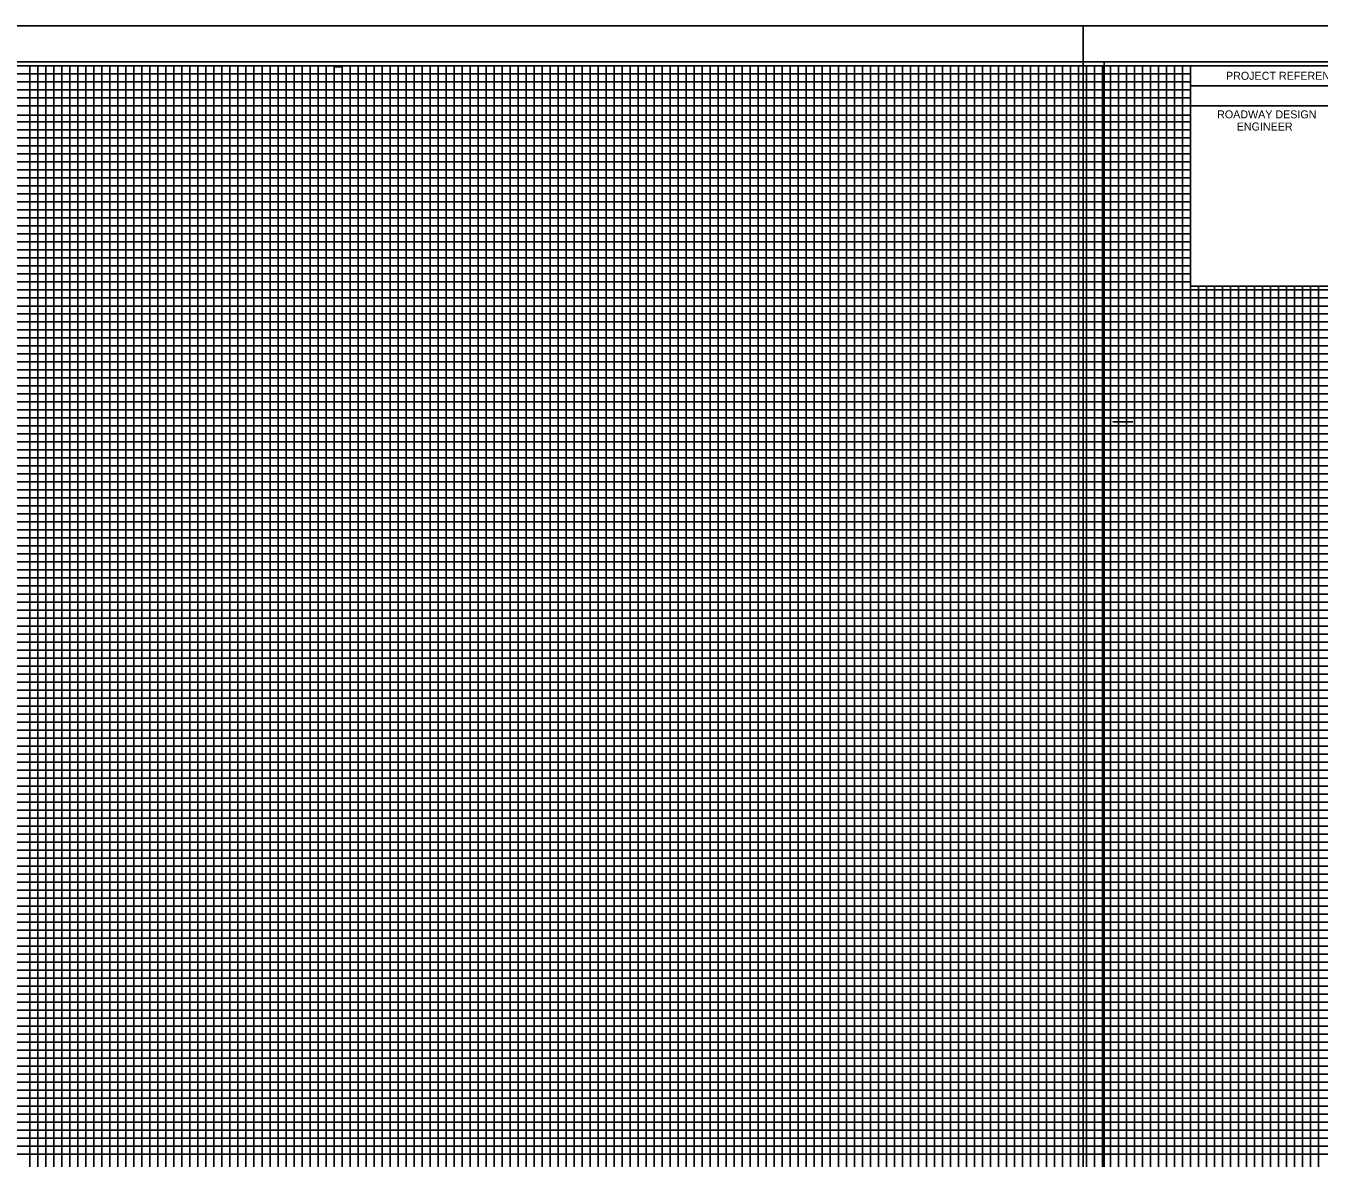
# Model space of a CAD drawing. Extents: x 2345490 to 2436403, y 465165 to 573888.
# Drawn here: x 2382289 to 2383097, y 510797 to 511504 of the extents above; entities that cross this region are included whole.
import ezdxf

# ---------------------------------------------------------------- set-up
doc = ezdxf.new("R2010")
doc.units = 0
for name, color, linetype in [('Old_Level_18', 7, 'Continuous'), ('Old_Level_40', 7, 'Continuous'), ('Old_Level_41', 7, 'Continuous'), ('Old_Level_42', 7, 'Continuous'), ('Old_Level_43', 7, 'Continuous'), ('Old_Level_44', 7, 'Continuous'), ('Old_Level_50', 7, 'Continuous'), ('Old_Level_51', 7, 'Continuous')]:
    doc.layers.add(name, color=color, linetype=linetype)

msp = doc.modelspace()

# ---------------------------------------------------------------- linework, layer by layer
at = {"layer": 'Old_Level_18'}
msp.add_lwpolyline([(2383216.79875, 511479.3835), (2381716.79875, 511479.3835), (2381716.79875, 510429.3835), (2383216.79875, 510429.3835)], close=True, dxfattribs=at)
at = {"layer": 'Old_Level_40'}
msp.add_line((2383016.74875, 511466.8335), (2383216.79875, 511466.8335), dxfattribs=at)
for points in [[(2383016.74875, 511479.3835), (2383216.79875, 511479.3835), (2383216.79875, 511454.3335), (2383016.74875, 511454.3335)], [(2383016.74875, 511454.3335), (2383116.79875, 511454.3335), (2383116.79875, 511341.8335), (2383016.74875, 511341.8335)]]:
    msp.add_lwpolyline(points, close=True, dxfattribs=at)
at = {"layer": 'Old_Level_41'}
msp.add_line((2382968.29875, 511256.8835), (2382980.79875, 511256.8835), dxfattribs=at)
for points in [[(2382291.79875, 510454.3835), (2382291.79875, 511479.3835), (2382341.79875, 511479.3835), (2382341.79875, 510454.3835)], [(2382316.79875, 510454.3835), (2382316.79875, 511479.3835), (2382366.79875, 511479.3835), (2382366.79875, 510454.3835)], [(2382391.79875, 510454.3835), (2382391.79875, 511479.3835), (2382441.79875, 511479.3835), (2382441.79875, 510454.3835)], [(2382416.79875, 510454.3835), (2382416.79875, 511479.3835), (2382466.79875, 511479.3835), (2382466.79875, 510454.3835)], [(2382491.79875, 510454.3835), (2382491.79875, 511479.3835), (2382541.79875, 511479.3835), (2382541.79875, 510454.3835)], [(2382516.79875, 510454.3835), (2382516.79875, 511479.3835), (2382566.79875, 511479.3835), (2382566.79875, 510454.3835)], [(2382591.79875, 510454.3835), (2382591.79875, 511479.3835), (2382641.79875, 511479.3835), (2382641.79875, 510454.3835)], [(2382616.79875, 510454.3835), (2382616.79875, 511479.3835), (2382666.79875, 511479.3835), (2382666.79875, 510454.3835)], [(2382691.79875, 510454.3835), (2382691.79875, 511479.3835), (2382741.79875, 511479.3835), (2382741.79875, 510454.3835)], [(2382716.79875, 510454.3835), (2382716.79875, 511479.3835), (2382766.79875, 511479.3835), (2382766.79875, 510454.3835)], [(2382791.79875, 510454.3835), (2382791.79875, 511479.3835), (2382841.79875, 511479.3835), (2382841.79875, 510454.3835)], [(2382816.79875, 510454.3835), (2382816.79875, 511479.3835), (2382866.79875, 511479.3835), (2382866.79875, 510454.3835)], [(2382891.79875, 510454.3835), (2382891.79875, 511479.3835), (2382941.79875, 511479.3835), (2382941.79875, 510454.3835)], [(2382916.79875, 510454.3835), (2382916.79875, 511479.3835), (2382966.79875, 511479.3835), (2382966.79875, 510454.3835)], [(2382991.79875, 510454.3835), (2382991.79875, 511479.3835)], [(2383016.79875, 510454.3835), (2383016.79875, 511479.3835), (2383043.09875, 511479.3835)], [(2381716.79875, 511429.3835), (2383016.74875, 511429.3835)], [(2383016.74875, 511379.3835), (2381716.79875, 511379.3835), (2381716.79875, 511329.3335), (2383216.79875, 511329.3335)], [(2383216.79875, 511304.3835), (2381716.79875, 511304.3835), (2381716.79875, 511354.3835), (2383016.74875, 511354.3835)], [(2383041.79875, 511341.8335), (2383041.79875, 510454.3835), (2383091.79875, 510454.3835), (2383091.79875, 511341.8335)], [(2383216.79875, 511279.3835), (2381716.79875, 511279.3835), (2381716.79875, 511229.3835), (2383216.79875, 511229.3835)], [(2383216.79875, 511204.3835), (2381716.79875, 511204.3835), (2381716.79875, 511254.3835), (2383216.79875, 511254.3835)], [(2383216.79875, 511179.3835), (2381716.79875, 511179.3835), (2381716.79875, 511129.3835), (2383216.79875, 511129.3835)], [(2383216.79875, 511079.3835), (2381716.79875, 511079.3835), (2381716.79875, 511029.3835), (2383216.79875, 511029.3835)], [(2383216.79875, 510979.3835), (2381716.79875, 510979.3835), (2381716.79875, 510929.3835), (2383216.79875, 510929.3835)], [(2383216.79875, 510879.3835), (2381716.79875, 510879.3835), (2381716.79875, 510829.3835), (2383216.79875, 510829.3835)], [(2383216.79875, 510804.3835), (2381716.79875, 510804.3835), (2381716.79875, 510854.3835), (2383216.79875, 510854.3835)]]:
    msp.add_lwpolyline(points, dxfattribs=at)
at = {"layer": 'Old_Level_42'}
for points in [[(2383016.74875, 511404.3835), (2381716.89875, 511404.3835), (2381716.89875, 511454.3335), (2383016.74875, 511454.3335)], [(2383066.79875, 511341.8335), (2383066.79875, 510454.3835), (2383116.79875, 510454.3835), (2383116.79875, 511341.8335)], [(2383216.79875, 511104.3835), (2381716.79875, 511104.3835), (2381716.79875, 511154.3835), (2383216.79875, 511154.3835)], [(2383216.79875, 511004.3835), (2381716.79875, 511004.3835), (2381716.79875, 511054.3835), (2383216.79875, 511054.3835)], [(2383216.79875, 510904.3835), (2381716.79875, 510904.3835), (2381716.79875, 510954.3835), (2383216.79875, 510954.3835)]]:
    msp.add_lwpolyline(points, dxfattribs=at)
at = {"layer": 'Old_Level_43'}
for p, q in [((2383166.79875, 511299.3835), (2381766.79875, 511299.3835)), ((2381766.79875, 511294.3835), (2383166.79875, 511294.3835)), ((2383166.79875, 511274.3835), (2381766.79875, 511274.3835))]:
    msp.add_line(p, q, dxfattribs=at)
for points in [[(2382296.79875, 510454.3835), (2382296.79875, 511479.3835), (2382301.79875, 511479.3835), (2382301.79875, 510454.3835)], [(2382306.79875, 510454.3835), (2382306.79875, 511479.3835), (2382311.79875, 511479.3835), (2382311.79875, 510454.3835)], [(2382321.79875, 510454.3835), (2382321.79875, 511479.3835), (2382326.79875, 511479.3835), (2382326.79875, 510454.3835)], [(2382331.79875, 510454.3835), (2382331.79875, 511479.3835), (2382336.79875, 511479.3835), (2382336.79875, 510454.3835)], [(2382346.79875, 510454.3835), (2382346.79875, 511479.3835), (2382351.79875, 511479.3835), (2382351.79875, 510454.3835)], [(2382356.79875, 510454.3835), (2382356.79875, 511479.3835), (2382361.79875, 511479.3835), (2382361.79875, 510454.3835)], [(2382371.79875, 510454.3835), (2382371.79875, 511479.3835), (2382376.79875, 511479.3835), (2382376.79875, 510454.3835)], [(2382381.79875, 510454.3835), (2382381.79875, 511479.3835), (2382386.79875, 511479.3835), (2382386.79875, 510454.3835)], [(2382396.79875, 510454.3835), (2382396.79875, 511479.3835), (2382401.79875, 511479.3835), (2382401.79875, 510454.3835)], [(2382406.79875, 510454.3835), (2382406.79875, 511479.3835), (2382411.79875, 511479.3835), (2382411.79875, 510454.3835)], [(2382421.79875, 510454.3835), (2382421.79875, 511479.3835), (2382426.79875, 511479.3835), (2382426.79875, 510454.3835)], [(2382431.79875, 510454.3835), (2382431.79875, 511479.3835), (2382436.79875, 511479.3835), (2382436.79875, 510454.3835)], [(2382446.79875, 510454.3835), (2382446.79875, 511479.3835), (2382451.79875, 511479.3835), (2382451.79875, 510454.3835)], [(2382456.79875, 510454.3835), (2382456.79875, 511479.3835), (2382461.79875, 511479.3835), (2382461.79875, 510454.3835)], [(2382471.79875, 510454.3835), (2382471.79875, 511479.3835), (2382476.79875, 511479.3835), (2382476.79875, 510454.3835)], [(2382481.79875, 510454.3835), (2382481.79875, 511478.7835), (2382486.79875, 511478.7835), (2382486.79875, 510454.3835)], [(2382496.79875, 510454.3835), (2382496.79875, 511479.3835), (2382501.79875, 511479.3835), (2382501.79875, 510454.3835)], [(2382506.79875, 510454.3835), (2382506.79875, 511479.3835), (2382511.79875, 511479.3835), (2382511.79875, 510454.3835)], [(2382521.79875, 510454.3835), (2382521.79875, 511479.3835), (2382526.79875, 511479.3835), (2382526.79875, 510454.3835)], [(2382531.79875, 510454.3835), (2382531.79875, 511479.3835), (2382536.79875, 511479.3835), (2382536.79875, 510454.3835)], [(2382546.79875, 510454.3835), (2382546.79875, 511479.3835), (2382551.79875, 511479.3835), (2382551.79875, 510454.3835)], [(2382556.79875, 510454.3835), (2382556.79875, 511479.3835), (2382561.79875, 511479.3835), (2382561.79875, 510454.3835)], [(2382571.79875, 510454.3835), (2382571.79875, 511479.3835), (2382576.79875, 511479.3835), (2382576.79875, 510454.3835)], [(2382581.79875, 510454.3835), (2382581.79875, 511479.3835), (2382586.79875, 511479.3835), (2382586.79875, 510454.3835)], [(2382596.79875, 510454.3835), (2382596.79875, 511479.3835), (2382601.79875, 511479.3835), (2382601.79875, 510454.3835)], [(2382606.79875, 510454.3835), (2382606.79875, 511479.3835), (2382611.79875, 511479.3835), (2382611.79875, 510454.3835)], [(2382621.79875, 510454.3835), (2382621.79875, 511479.3835), (2382626.79875, 511479.3835), (2382626.79875, 510454.3835)], [(2382631.79875, 510454.3835), (2382631.79875, 511479.3835), (2382636.79875, 511479.3835), (2382636.79875, 510454.3835)], [(2382646.79875, 510454.3835), (2382646.79875, 511479.3835), (2382651.79875, 511479.3835), (2382651.79875, 510454.3835)], [(2382656.79875, 510454.3835), (2382656.79875, 511479.3835), (2382661.79875, 511479.3835), (2382661.79875, 510454.3835)], [(2382671.79875, 510454.3835), (2382671.79875, 511479.3835), (2382676.79875, 511479.3835), (2382676.79875, 510454.3835)], [(2382681.79875, 510454.3835), (2382681.79875, 511479.3835), (2382686.79875, 511479.3835), (2382686.79875, 510454.3835)], [(2382696.79875, 510454.3835), (2382696.79875, 511479.3835), (2382701.79875, 511479.3835), (2382701.79875, 510454.3835)], [(2382706.79875, 510454.3835), (2382706.79875, 511479.3835), (2382711.79875, 511479.3835), (2382711.79875, 510454.3835)], [(2382721.79875, 510454.3835), (2382721.79875, 511479.3835), (2382726.79875, 511479.3835), (2382726.79875, 510454.3835)], [(2382731.79875, 510454.3835), (2382731.79875, 511479.3835), (2382736.79875, 511479.3835), (2382736.79875, 510454.3835)], [(2382746.79875, 510454.3835), (2382746.79875, 511479.3835), (2382751.79875, 511479.3835), (2382751.79875, 510454.3835)], [(2382756.79875, 510454.3835), (2382756.79875, 511479.3835), (2382761.79875, 511479.3835), (2382761.79875, 510454.3835)], [(2382771.79875, 510454.3835), (2382771.79875, 511479.3835), (2382776.79875, 511479.3835), (2382776.79875, 510454.3835)], [(2382781.79875, 510454.3835), (2382781.79875, 511479.3835), (2382786.79875, 511479.3835), (2382786.79875, 510454.3835)], [(2382796.79875, 510454.3835), (2382796.79875, 511479.3835), (2382801.79875, 511479.3835), (2382801.79875, 510454.3835)], [(2382806.79875, 510454.3835), (2382806.79875, 511479.3835), (2382811.79875, 511479.3835), (2382811.79875, 510454.3835)], [(2382821.79875, 510454.3835), (2382821.79875, 511479.3835), (2382826.79875, 511479.3835), (2382826.79875, 510454.3835)], [(2382831.79875, 510454.3835), (2382831.79875, 511479.3835), (2382836.79875, 511479.3835), (2382836.79875, 510454.3835)], [(2382846.79875, 510454.3835), (2382846.79875, 511479.3835), (2382851.79875, 511479.3835), (2382851.79875, 510454.3835)], [(2382856.79875, 510454.3835), (2382856.79875, 511479.3835), (2382861.79875, 511479.3835), (2382861.79875, 510454.3835)], [(2382871.79875, 510454.3835), (2382871.79875, 511479.3835), (2382876.79875, 511479.3835), (2382876.79875, 510454.3835)], [(2382881.79875, 510454.3835), (2382881.79875, 511479.3835), (2382886.79875, 511479.3835), (2382886.79875, 510454.3835)], [(2382896.79875, 510454.3835), (2382896.79875, 511479.3835), (2382901.79875, 511479.3835), (2382901.79875, 510454.3835)], [(2382906.79875, 510454.3835), (2382906.79875, 511479.3835), (2382911.79875, 511479.3835), (2382911.79875, 510454.3835)], [(2382921.79875, 510454.3835), (2382921.79875, 511479.3835), (2382926.79875, 511479.3835), (2382926.79875, 510454.3835)], [(2382931.79875, 510454.3835), (2382931.79875, 511479.3835), (2382936.79875, 511479.3835), (2382936.79875, 510454.3835)], [(2382946.79875, 510454.3835), (2382946.79875, 511479.3835), (2382951.79875, 511479.3835), (2382951.79875, 510454.3835)], [(2382956.79875, 510454.3835), (2382956.79875, 511479.3835), (2382961.79875, 511479.3835), (2382961.79875, 510454.3835)], [(2382971.79875, 510454.3835), (2382971.79875, 511479.3835), (2382976.79875, 511479.3835), (2382976.79875, 510454.3835)], [(2382981.79875, 510454.3835), (2382981.79875, 511479.3835), (2382986.79875, 511479.3835), (2382986.79875, 510454.3835)], [(2382996.79875, 510454.3835), (2382996.79875, 511479.3835), (2383001.79875, 511479.3835), (2383001.79875, 510454.3835)], [(2383006.79875, 510454.3835), (2383006.79875, 511479.3835), (2383011.79875, 511479.3835), (2383011.79875, 510454.3835)], [(2383016.74875, 511474.3835), (2381766.79875, 511474.3835), (2381766.79875, 511469.3835), (2383016.74875, 511469.3835)], [(2383016.74875, 511464.3835), (2381766.79875, 511464.3835), (2381766.79875, 511459.3835), (2383016.74875, 511459.3835)], [(2383016.74875, 511448.6335), (2381767.79875, 511448.6335), (2381767.79875, 511444.3835), (2383016.74875, 511444.3835)], [(2383016.74875, 511439.3835), (2381766.79875, 511439.3835), (2381766.79875, 511434.3835), (2383016.74875, 511434.3835)], [(2383016.74875, 511424.3835), (2381766.79875, 511424.3835), (2381766.79875, 511419.3835), (2383016.74875, 511419.3835)], [(2383016.74875, 511414.3835), (2381766.79875, 511414.3835), (2381766.79875, 511409.3835), (2383016.74875, 511409.3835)], [(2383016.74875, 511399.3835), (2381766.79875, 511399.3835), (2381766.79875, 511394.3835), (2383016.74875, 511394.3835)], [(2383016.74875, 511389.3835), (2381766.79875, 511389.3835), (2381766.79875, 511384.3835), (2383016.74875, 511384.3835)], [(2383016.74875, 511374.3835), (2381766.79875, 511374.3835), (2381766.79875, 511369.3835), (2383016.74875, 511369.3835)], [(2383016.74875, 511364.3835), (2381766.79875, 511364.3835), (2381766.79875, 511359.3835), (2383016.74875, 511359.3835)], [(2383016.74875, 511349.3835), (2381766.79875, 511349.3835), (2381766.79875, 511344.3835), (2383016.74875, 511344.3835)], [(2383166.79875, 511339.3835), (2381766.79875, 511339.3835), (2381766.79875, 511339.3835), (2381766.79875, 511319.3835), (2383166.79875, 511319.3835)], [(2383021.79875, 510454.3835), (2383021.79875, 511341.8335)], [(2383026.79875, 511341.8335), (2383026.79875, 510454.3835), (2383031.79875, 510454.3835), (2383031.79875, 511341.8335)], [(2383036.79875, 511341.8335), (2383036.79875, 510454.3835), (2383046.79875, 510454.3835), (2383046.79875, 511341.8335)], [(2383051.79875, 511341.8335), (2383051.79875, 510454.3835), (2383056.79875, 510454.3835), (2383056.79875, 511341.8335)], [(2383061.79875, 511341.8335), (2383061.79875, 510454.3835), (2383071.79875, 510454.3835), (2383071.79875, 511341.8335)], [(2383076.79875, 511341.8335), (2383076.79875, 510454.3835), (2383081.79875, 510454.3835), (2383081.79875, 511341.8335)], [(2383086.79875, 511341.8335), (2383086.79875, 510454.3835), (2383096.79875, 510454.3835), (2383096.79875, 511341.8335)], [(2381766.79875, 511334.3835), (2383166.79875, 511334.3835)], [(2383166.79875, 511324.3835), (2381766.79875, 511324.3835)], [(2383166.79875, 511314.3835), (2381766.79875, 511314.3835), (2381766.79875, 511309.3835), (2383166.79875, 511309.3835)], [(2383166.79875, 511289.3835), (2381766.79875, 511289.3835), (2381766.79875, 511284.3835), (2383166.79875, 511284.3835)], [(2383166.79875, 511269.3835), (2381766.79875, 511269.3835), (2381766.79875, 511264.3835), (2383166.79875, 511264.3835)], [(2383166.79875, 511259.3835), (2381766.79875, 511259.3835)], [(2381766.79875, 511249.3835), (2383166.79875, 511249.3835)], [(2383166.79875, 511244.3835), (2381766.79875, 511244.3835), (2381766.79875, 511239.3835), (2383166.79875, 511239.3835)], [(2383166.79875, 511234.3835), (2381766.79875, 511234.3835), (2381766.79875, 511224.3835), (2383166.79875, 511224.3835)], [(2383166.79875, 511219.3835), (2381766.79875, 511219.3835), (2381766.79875, 511214.3835), (2383166.79875, 511214.3835)], [(2383166.79875, 511209.3835), (2381766.79875, 511209.3835), (2381766.79875, 511199.3835), (2383166.79875, 511199.3835)], [(2383166.79875, 511194.3835), (2381766.79875, 511194.3835), (2381766.79875, 511189.3835), (2383166.79875, 511189.3835)], [(2383166.79875, 511184.3835), (2381766.79875, 511184.3835), (2381766.79875, 511174.3835), (2383166.79875, 511174.3835)], [(2383166.79875, 511169.3835), (2381766.79875, 511169.3835), (2381766.79875, 511164.3835), (2383166.79875, 511164.3835)], [(2383166.79875, 511159.3835), (2381766.79875, 511159.3835), (2381766.79875, 511149.3835), (2383166.79875, 511149.3835)], [(2383166.79875, 511144.3835), (2381766.79875, 511144.3835), (2381766.79875, 511139.3835), (2383166.79875, 511139.3835)], [(2383166.79875, 511134.3835), (2381766.79875, 511134.3835), (2381766.79875, 511124.3835), (2383166.79875, 511124.3835)], [(2383166.79875, 511119.3835), (2381766.79875, 511119.3835), (2381766.79875, 511114.3835), (2383166.79875, 511114.3835)], [(2383166.79875, 511109.3835), (2381766.79875, 511109.3835), (2381766.79875, 511099.3835), (2383166.79875, 511099.3835)], [(2383166.79875, 511094.3835), (2381766.79875, 511094.3835), (2381766.79875, 511089.3835), (2383166.79875, 511089.3835)], [(2383166.79875, 511084.3835), (2381766.79875, 511084.3835), (2381766.79875, 511074.3835), (2383166.79875, 511074.3835)], [(2383166.79875, 511069.3835), (2381766.79875, 511069.3835), (2381766.79875, 511064.3835), (2383166.79875, 511064.3835)], [(2383166.79875, 511059.3835), (2381766.79875, 511059.3835), (2381766.79875, 511049.3835), (2383166.79875, 511049.3835)], [(2383166.79875, 511044.3835), (2381766.79875, 511044.3835), (2381766.79875, 511039.3835), (2383166.79875, 511039.3835)], [(2383166.79875, 511034.3835), (2381766.79875, 511034.3835), (2381766.79875, 511024.3835), (2383166.79875, 511024.3835)], [(2383166.79875, 511019.3835), (2381766.79875, 511019.3835), (2381766.79875, 511014.3835), (2383166.79875, 511014.3835)], [(2383166.79875, 511009.3835), (2381766.79875, 511009.3835), (2381766.79875, 510999.3835), (2383166.79875, 510999.3835)], [(2383166.79875, 510994.3835), (2381766.79875, 510994.3835), (2381766.79875, 510989.3835), (2383166.79875, 510989.3835)], [(2383166.79875, 510984.3835), (2381766.79875, 510984.3835), (2381766.79875, 510974.3835), (2383166.79875, 510974.3835)], [(2383166.79875, 510969.3835), (2381766.79875, 510969.3835), (2381766.79875, 510964.3835), (2383166.79875, 510964.3835)], [(2383166.79875, 510959.3835), (2381766.79875, 510959.3835)], [(2381766.79875, 510949.3835), (2383166.79875, 510949.3835)], [(2383166.79875, 510944.3835), (2381766.79875, 510944.3835), (2381766.79875, 510939.3835), (2383166.79875, 510939.3835)], [(2383166.79875, 510934.3835), (2381766.79875, 510934.3835), (2381766.79875, 510924.3835), (2383166.79875, 510924.3835)], [(2383166.79875, 510919.3835), (2381766.79875, 510919.3835), (2381766.79875, 510914.3835), (2383166.79875, 510914.3835)], [(2383166.79875, 510909.3835), (2381766.79875, 510909.3835), (2381766.79875, 510899.3835), (2383166.79875, 510899.3835)], [(2383166.79875, 510894.3835), (2381766.79875, 510894.3835), (2381766.79875, 510889.3835), (2383166.79875, 510889.3835)], [(2383166.79875, 510884.3835), (2381766.79875, 510884.3835), (2381766.79875, 510874.3835), (2383166.79875, 510874.3835)], [(2383166.79875, 510869.3835), (2381766.79875, 510869.3835), (2381766.79875, 510864.3835), (2383166.79875, 510864.3835)], [(2383166.79875, 510859.3835), (2381766.79875, 510859.3835), (2381766.79875, 510849.3835), (2383166.79875, 510849.3835)], [(2383166.79875, 510844.3835), (2381766.79875, 510844.3835), (2381766.79875, 510839.3835), (2383166.79875, 510839.3835)], [(2383166.79875, 510834.3835), (2381766.79875, 510834.3835), (2381766.79875, 510824.3835), (2383166.79875, 510824.3835)], [(2383166.79875, 510819.3835), (2381766.79875, 510819.3835), (2381766.79875, 510814.3835), (2383166.79875, 510814.3835)], [(2383166.79875, 510809.3835), (2381766.79875, 510809.3835), (2381766.79875, 510799.3835), (2383166.79875, 510799.3835)]]:
    msp.add_lwpolyline(points, dxfattribs=at)
at = {"layer": 'Old_Level_50'}
for points in [[(2383229.29875, 511481.9335), (2381562.79875, 511481.9335), (2381562.79875, 510426.8335), (2383229.29875, 510426.8335)], [(2384629.29875, 511481.9335), (2382962.79875, 511481.9335), (2382962.79875, 510426.8335), (2384629.29875, 510426.8335)]]:
    msp.add_lwpolyline(points, close=True, dxfattribs=at)
at = {"layer": 'Old_Level_51'}
for points in [[(2383233.79875, 511504.3835), (2381549.79875, 511504.3835), (2381549.79875, 510404.3835), (2383233.79875, 510404.3835)], [(2384633.79875, 511504.3835), (2382949.79875, 511504.3835), (2382949.79875, 510404.3835), (2384633.79875, 510404.3835)]]:
    msp.add_lwpolyline(points, close=True, dxfattribs=at)

# ---------------------------------------------------------------- texts
at = {"layer": 'Old_Level_44'}
for s, p in [('PROJECT REFERENCE NO.', (2383038.94875, 511470.6835)), ('ROADWAY DESIGN', (2383033.39875, 511446.5835)), ('ENGINEER', (2383045.64875, 511438.9835))]:
    msp.add_text(s, height=5.0001, dxfattribs=at).set_placement(p)

doc.saveas('drawing.dxf')
